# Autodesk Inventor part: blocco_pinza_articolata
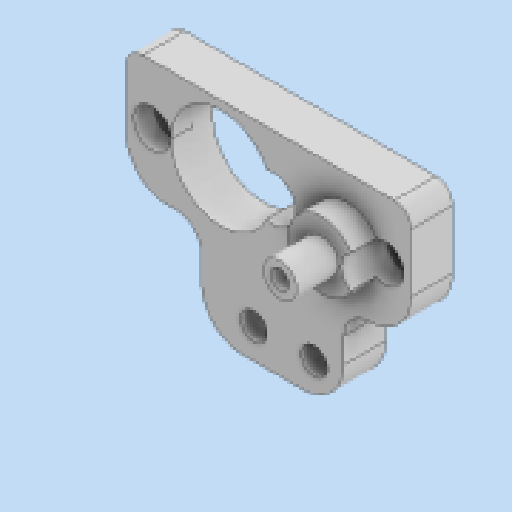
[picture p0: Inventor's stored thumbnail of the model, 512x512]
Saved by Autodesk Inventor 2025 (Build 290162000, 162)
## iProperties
Created: 2026-03
Part Number: blocco_pinza_articolata
Material: Generico
Document SubType Name: Modeling
Designer: R5800u
Density: 1 g/cm^3
Appearance: Default
Author: R5800u
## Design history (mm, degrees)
sketch "Schizzo1"
  geometry: L1 (0, 0)-(0, 11.705) reference; L2 (0, 0)-(6.476, 0) reference; L3 (-17, 7)-(17, 7); L4 (17, 7)-(17, -7); L5 (17, -7)-(-17, -7); L6 (-17, -7)-(-17, 7); L7 (0, -7)-(-6.5, -7); L8 (-6.5, -7)-(-6.5, -18); L9 (-6.5, -18)-(0, -18); L10 (0, -18)-(0, -7); L11 (0, -7)-(9.5, -7); L12 (9.5, -7)-(9.5, -18); L13 (9.5, -18)-(0, -18); L14 (0, -18)-(0, -7); L15 (-17, -7)-(-6.5, -18); L16 (17, -7)-(9.5, -18); A1 r 5.8 centre (-5.65, 0) between (-0.341, 2.336) and (-0.341, -2.336) reference; A2 r 2.5 centre (0.55, 0) between (-0.341, -2.336) and (-0.341, 2.336) reference; A3 r 6 centre (-5.65, 0) between (-0.235, 2.583) and (-0.235, -2.583); A4 r 2.7 centre (0.55, 0) between (-0.235, -2.583) and (-0.235, 2.583); 6 further points
  constraints: 32 end point, 6 parallel, 5 horizontal, 4 point on circle, 3 perpendicular, 2 centre point, 2 vertical, 1 midpoint, 1 point on line, 6 other
  dimensions: "d0" = 34 distance of L4.end L5.end; "d1" = 14 distance of L3.end L4.end; "d2" = 0.2 radial gap between concentric circles of A1 A3; "d18" = 6.5 distance of L9.end L8.end; "d19" = 11 distance of L8.end L7.end; "d20" = 9.5 distance of L12.end L13.end
  node "Riferimento1"
  node "Riferimento2"
node "Piano di lavoro1"
extrude "Estrusione1" new body sketch "Schizzo1" stored distance "d3" = 10; taper "d4" = 0 deg
sketch "Schizzo2"
  geometry: A1 r 1 centre (30.9, 7) between (31.7, 7.6) and (31.7, 6.4) reference; A2 r 1 centre (3.1, 7) between (2.3, 6.4) and (2.3, 7.6) reference; 1 further point
hole "Foro1" sketch "Schizzo2" at (30.9, 7), (3.1, 7) diameter "d5" = 2.7; stored, may be unused: countersink angle "d9" = 90 deg, drill point angle "d11" = 118 deg; dims "d6" = 6, "d7" = 4.5, "d8" = 2.5, "d10" = 8
sketch "Schizzo3"
  geometry: C1 r 2 at (26.35, 7); A1 r 6.25 centre (26.35, 7) between (27.71, 0.9) and (28.34, 1.075) reference; 1 further point
  constraints: 1 centre point, 1 coincident
  dimensions: "d12" = 4 diameter of C1
extrude "Estrusione2" join sketch "Schizzo3" distance "d13" = 8; taper "d14" = 0 deg
sketch "Schizzo4"
  geometry: C1 r 2 at (26.35, 7) reference; C2 r 4 at (26.35, 7); C3 r 2.25 at (30.9, 7) reference; 3 further points
  constraints: 1 centre point, 1 coincident
  dimensions: "d15" = 8 diameter of C2
node "Piano di lavoro2"
extrude "Estrusione3" join sketch "Schizzo4" stored distance "d16" = 9; taper "d17" = 0 deg
sketch "Schizzo5"
  geometry: L1 (26.5, -25)-(10.5, -25) reference; L2 (26.35, -7)-(11.35, -7); L3 (18.85, -7)-(18.85, -21.4); L4 (22.45, -21.4)-(18.85, -21.4); L5 (18.85, -21.4)-(15.25, -21.4); C1 r 2 at (26.35, -7) reference; C2 r 2.25 at (11.35, -7) reference; 2 further points
  constraints: 8 end point, 3 horizontal, 1 midpoint, 1 vertical
  dimensions: "d29" = 14.4 distance of L3.start L3.end; "d31" = 3.6 distance of L3.end L5.end; "d34" = 3.6 distance of L4.start L3.end
hole "Foro2" sketch "Schizzo5" at (15.25, -21.4), (22.45, -21.4) diameter "d22" = 3.2; stored, may be unused: countersink angle "d26" = 90 deg, drill point angle "d28" = 118 deg; dims "d23" = 6, "d24" = 6.5, "d25" = 3.4, "d27" = 8
fillet "Raccordo2" dims "d33" = 2
fillet "Raccordo3" dims "d35" = 5
sketch "Schizzo6"
  geometry: C1 r 2 at (-9.35, 0) reference; 1 further point
hole "Foro3" sketch "Schizzo6" at (-9.35, 0) diameter "d37" = 2.2; stored, may be unused: countersink angle "d41" = 90 deg, drill point angle "d43" = 118 deg; dims "d38" = 6, "d39" = 4.4, "d40" = 3.5, "d42" = 8
fillet "Raccordo6" dims "d45" = 3
node "Solido1"
node "Riferimento3"
node "Riferimento4"
node "Riferimento5"
node "Riferimento6"
node "Linea chiusa proiettata1"
other parameters: "d30" = 4
